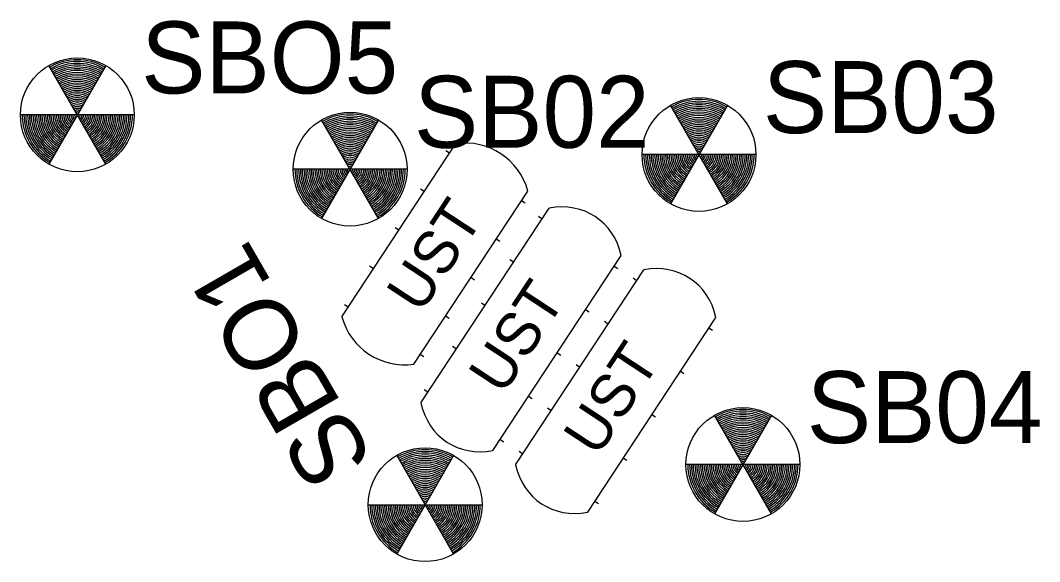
# Model space of a CAD drawing. Extents: x 557444 to 557718, y 506539 to 506965.
# Drawn here: x 557447.4 to 557504, y 506628.1 to 506658.1 of the extents above; entities that cross this region are included whole.
import ezdxf

# ---------------------------------------------------------------- set-up
doc = ezdxf.new("R2010")
doc.units = 0
doc.layers.add('Exist Roads EOP Cogo Number', color=7, linetype='Continuous')
doc.layers.add('Exist Roads EOP Cogo Point CELL', color=7, linetype='Continuous')

msp = doc.modelspace()

# ---------------------------------------------------------------- linework, layer by layer
at = {"layer": 'Exist Roads EOP Cogo Number'}
for p, q in [((557465.227, 506641.678), (557471.561, 506651.301)), ((557471.209, 506650.766), (557471.008, 506650.898)), ((557469.236, 506639.039), (557475.57, 506648.661)), ((557469.801, 506648.628), (557469.601, 506648.76)), ((557475.419, 506647.995), (557475.218, 506648.127)), ((557469.617, 506636.887), (557476.743, 506647.712)), ((557476.347, 506647.111), (557476.147, 506647.243)), ((557468.394, 506646.489), (557468.193, 506646.621)), ((557474.011, 506645.857), (557473.811, 506645.989)), ((557473.627, 506634.248), (557480.752, 506645.073)), ((557474.764, 506644.705), (557474.563, 506644.837)), ((557466.977, 506644.352), (557466.777, 506644.484)), ((557474.877, 506633.457), (557482.002, 506644.282)), ((557480.557, 506644.34), (557480.357, 506644.472)), ((557472.604, 506643.718), (557472.403, 506643.85)), ((557481.606, 506643.681), (557481.406, 506643.813)), ((557465.579, 506642.213), (557465.378, 506642.345)), ((557473.18, 506642.299), (557472.98, 506642.431)), ((557478.974, 506641.934), (557478.773, 506642.066)), ((557471.196, 506641.58), (557470.996, 506641.712)), ((557478.886, 506630.818), (557486.012, 506641.643)), ((557480.023, 506641.275), (557479.822, 506641.407)), ((557485.816, 506640.91), (557485.616, 506641.042)), ((557469.789, 506639.442), (557469.588, 506639.574)), ((557471.587, 506639.895), (557471.387, 506640.027)), ((557477.39, 506639.528), (557477.19, 506639.66)), ((557478.439, 506638.87), (557478.239, 506639.002)), ((557484.233, 506638.504), (557484.032, 506638.636)), ((557470.013, 506637.488), (557469.813, 506637.62)), ((557475.807, 506637.123), (557475.606, 506637.255)), ((557476.846, 506636.465), (557476.646, 506636.597)), ((557482.649, 506636.099), (557482.449, 506636.231)), ((557474.223, 506634.717), (557474.023, 506634.849)), ((557475.272, 506634.059), (557475.072, 506634.19)), ((557481.066, 506633.693), (557480.865, 506633.825)), ((557479.482, 506631.287), (557479.282, 506631.419))]:
    msp.add_line(p, q, dxfattribs=at)
for centre, major_axis, ratio in [((557471.818, 506647.327), (-2.244, -3.409), 0.9375), ((557476.782, 506643.406), (-2.524, -3.835), 0.833333), ((557482.041, 506639.977), (-2.524, -3.835), 0.833333), ((557468.979, 506643.013), (2.244, 3.409), 0.9375), ((557473.588, 506638.553), (2.524, 3.835), 0.833333), ((557478.847, 506635.124), (2.524, 3.835), 0.833333)]:
    msp.add_ellipse(centre, major_axis=major_axis, ratio=ratio, start_param=2.463448, end_param=3.819737, dxfattribs=at)
at = {"layer": 'Exist Roads EOP Cogo Point CELL'}
for p, q in [((557452.123, 506650.157), (557448.961, 506655.634)), ((557452.123, 506655.634), (557448.961, 506650.157)), ((557486.649, 506647.951), (557483.487, 506653.428)), ((557486.649, 506653.428), (557483.487, 506647.951)), ((557453.704, 506652.895), (557447.38, 506652.895)), ((557467.273, 506647.137), (557464.111, 506652.614)), ((557467.273, 506652.614), (557464.111, 506647.137)), ((557488.23, 506650.69), (557481.906, 506650.69)), ((557468.854, 506649.875), (557462.53, 506649.875)), ((557489.089, 506630.729), (557485.927, 506636.206)), ((557489.089, 506636.206), (557485.927, 506630.729)), ((557468.279, 506633.974), (557471.441, 506628.497)), ((557471.441, 506633.974), (557468.279, 506628.497)), ((557490.67, 506633.468), (557484.346, 506633.468)), ((557466.698, 506631.236), (557473.022, 506631.236))]:
    msp.add_line(p, q, dxfattribs=at)
for centre in [(557450.542, 506652.895), (557485.068, 506650.69), (557465.692, 506649.875), (557487.508, 506633.468), (557469.86, 506631.236)]:
    msp.add_circle(centre, 3.162, dxfattribs=at)
for centre, radius, start, end in [((557450.542, 506652.895), 3.062, 60, 120), ((557450.542, 506652.895), 2.962, 60, 120), ((557450.542, 506652.895), 2.862, 60, 120), ((557450.542, 506652.895), 2.762, 60, 120), ((557450.542, 506652.895), 2.662, 60, 120), ((557450.542, 506652.895), 2.562, 60, 120), ((557450.542, 506652.895), 2.462, 60, 120), ((557450.542, 506652.895), 2.362, 60, 120), ((557450.542, 506652.895), 2.262, 60, 120), ((557450.542, 506652.895), 2.162, 60, 120), ((557450.542, 506652.895), 2.062, 60, 120), ((557450.542, 506652.895), 1.962, 60, 120), ((557450.542, 506652.895), 1.862, 60, 120), ((557450.542, 506652.895), 1.762, 60, 120), ((557450.542, 506652.895), 1.662, 60, 120), ((557450.542, 506652.895), 1.562, 60, 120), ((557450.542, 506652.895), 1.462, 60, 120), ((557450.542, 506652.895), 1.362, 60, 120), ((557450.542, 506652.895), 1.262, 60, 120), ((557450.542, 506652.895), 1.162, 60, 120), ((557450.542, 506652.895), 1.062, 60, 120), ((557450.542, 506652.895), 0.962, 60, 120), ((557450.542, 506652.895), 0.862, 60, 120), ((557450.542, 506652.895), 0.762, 60, 120), ((557485.068, 506650.69), 3.062, 60, 120), ((557450.542, 506652.895), 0.662, 60, 120), ((557450.542, 506652.895), 0.562, 60, 120), ((557450.542, 506652.895), 0.462, 60, 120), ((557450.542, 506652.895), 0.362, 60, 120), ((557450.542, 506652.895), 0.262, 60, 120), ((557485.068, 506650.69), 2.962, 60, 120), ((557485.068, 506650.69), 2.862, 60, 120), ((557485.068, 506650.69), 2.762, 60, 120), ((557485.068, 506650.69), 2.662, 60, 120), ((557485.068, 506650.69), 2.562, 60, 120), ((557485.068, 506650.69), 2.462, 60, 120), ((557450.542, 506652.895), 3.062, 180, 240), ((557450.542, 506652.895), 2.962, 180, 240), ((557450.542, 506652.895), 2.862, 180, 240), ((557450.542, 506652.895), 2.762, 180, 240), ((557450.542, 506652.895), 2.662, 180, 240), ((557450.542, 506652.895), 2.562, 180, 240), ((557450.542, 506652.895), 2.462, 180, 240), ((557450.542, 506652.895), 2.362, 180, 240), ((557450.542, 506652.895), 2.262, 180, 240), ((557450.542, 506652.895), 2.162, 180, 240), ((557450.542, 506652.895), 2.062, 180, 240), ((557450.542, 506652.895), 1.962, 180, 240), ((557450.542, 506652.895), 1.862, 180, 240), ((557450.542, 506652.895), 1.762, 180, 240), ((557450.542, 506652.895), 1.662, 180, 240), ((557450.542, 506652.895), 1.562, 180, 240), ((557450.542, 506652.895), 1.462, 180, 240), ((557450.542, 506652.895), 1.362, 180, 240), ((557450.542, 506652.895), 1.262, 180, 240), ((557450.542, 506652.895), 1.162, 180, 240), ((557450.542, 506652.895), 1.062, 180, 240), ((557450.542, 506652.895), 0.962, 180, 240), ((557450.542, 506652.895), 0.862, 180, 240), ((557450.542, 506652.895), 0.762, 180, 240), ((557450.542, 506652.895), 0.662, 180, 240), ((557450.542, 506652.895), 0.562, 180, 240), ((557450.542, 506652.895), 0.462, 180, 240), ((557450.542, 506652.895), 0.362, 180, 240), ((557450.542, 506652.895), 0.262, 180, 240), ((557450.542, 506652.895), 0.162, 180, 240), ((557450.542, 506652.895), 0.162, 60, 120), ((557450.542, 506652.895), 0.162, 300, 0), ((557450.542, 506652.895), 0.262, 300, 0), ((557450.542, 506652.895), 0.362, 300, 0), ((557450.542, 506652.895), 0.462, 300, 0), ((557450.542, 506652.895), 0.562, 300, 360), ((557450.542, 506652.895), 0.662, 300, 0), ((557450.542, 506652.895), 0.762, 300, 360), ((557450.542, 506652.895), 0.862, 300, 0), ((557450.542, 506652.895), 0.962, 300, 0), ((557450.542, 506652.895), 1.062, 300, 0), ((557450.542, 506652.895), 1.162, 300, 0), ((557450.542, 506652.895), 1.262, 300, 0), ((557450.542, 506652.895), 1.362, 300, 0), ((557450.542, 506652.895), 1.462, 300, 0), ((557450.542, 506652.895), 1.562, 300, 0), ((557450.542, 506652.895), 1.662, 300, 0), ((557450.542, 506652.895), 1.762, 300, 0), ((557450.542, 506652.895), 1.862, 300, 0), ((557450.542, 506652.895), 1.962, 300, 0), ((557450.542, 506652.895), 2.062, 300, 360), ((557450.542, 506652.895), 2.162, 300, 0), ((557450.542, 506652.895), 2.262, 300, 0), ((557450.542, 506652.895), 2.362, 300, 0), ((557450.542, 506652.895), 2.462, 300, 0), ((557450.542, 506652.895), 2.562, 300, 0), ((557450.542, 506652.895), 2.662, 300, 0), ((557450.542, 506652.895), 2.762, 300, 360), ((557450.542, 506652.895), 2.862, 300, 0), ((557450.542, 506652.895), 2.962, 300, 0), ((557450.542, 506652.895), 3.062, 300, 0), ((557465.692, 506649.875), 3.062, 60, 120), ((557465.692, 506649.875), 2.962, 60, 120), ((557465.692, 506649.875), 2.862, 60, 120), ((557465.692, 506649.875), 2.762, 60, 120), ((557465.692, 506649.875), 2.662, 60, 120), ((557485.068, 506650.69), 2.362, 60, 120), ((557485.068, 506650.69), 2.262, 60, 120), ((557485.068, 506650.69), 2.162, 60, 120), ((557485.068, 506650.69), 2.062, 60, 120), ((557485.068, 506650.69), 1.962, 60, 120), ((557485.068, 506650.69), 1.862, 60, 120), ((557465.692, 506649.875), 2.562, 60, 120), ((557465.692, 506649.875), 2.462, 60, 120), ((557465.692, 506649.875), 2.362, 60, 120), ((557465.692, 506649.875), 2.262, 60, 120), ((557465.692, 506649.875), 2.162, 60, 120), ((557485.068, 506650.69), 1.762, 60, 120), ((557485.068, 506650.69), 1.662, 60, 120), ((557485.068, 506650.69), 1.562, 60, 120), ((557485.068, 506650.69), 1.462, 60, 120), ((557485.068, 506650.69), 1.362, 60, 120), ((557465.692, 506649.875), 2.062, 60, 120), ((557465.692, 506649.875), 1.962, 60, 120), ((557465.692, 506649.875), 1.862, 60, 120), ((557465.692, 506649.875), 1.762, 60, 120), ((557465.692, 506649.875), 1.662, 60, 120), ((557465.692, 506649.875), 1.562, 60, 120), ((557485.068, 506650.69), 1.262, 60, 120), ((557485.068, 506650.69), 1.162, 60, 120), ((557485.068, 506650.69), 1.062, 60, 120), ((557485.068, 506650.69), 0.962, 60, 120), ((557485.068, 506650.69), 0.862, 60, 120), ((557485.068, 506650.69), 0.762, 60, 120), ((557465.692, 506649.875), 1.462, 60, 120), ((557465.692, 506649.875), 1.362, 60, 120), ((557465.692, 506649.875), 1.262, 60, 120), ((557465.692, 506649.875), 1.162, 60, 120), ((557465.692, 506649.875), 1.062, 60, 120), ((557465.692, 506649.875), 0.962, 60, 120), ((557485.068, 506650.69), 0.662, 60, 120), ((557485.068, 506650.69), 0.562, 60, 120), ((557485.068, 506650.69), 0.462, 60, 120), ((557485.068, 506650.69), 0.362, 60, 120), ((557485.068, 506650.69), 0.262, 60, 120), ((557485.068, 506650.69), 0.162, 60, 120), ((557465.692, 506649.875), 0.862, 60, 120), ((557465.692, 506649.875), 0.762, 60, 120), ((557465.692, 506649.875), 0.662, 60, 120), ((557465.692, 506649.875), 0.562, 60, 120), ((557465.692, 506649.875), 0.462, 60, 120), ((557485.068, 506650.69), 3.062, 180, 240), ((557485.068, 506650.69), 2.962, 180, 240), ((557485.068, 506650.69), 2.862, 180, 240), ((557485.068, 506650.69), 2.762, 180, 240), ((557485.068, 506650.69), 2.662, 180, 240), ((557485.068, 506650.69), 2.562, 180, 240), ((557485.068, 506650.69), 2.462, 180, 240), ((557485.068, 506650.69), 2.362, 180, 240), ((557485.068, 506650.69), 2.262, 180, 240), ((557485.068, 506650.69), 2.162, 180, 240), ((557485.068, 506650.69), 2.062, 180, 240), ((557485.068, 506650.69), 1.962, 180, 240), ((557485.068, 506650.69), 1.862, 180, 240), ((557485.068, 506650.69), 1.762, 180, 240), ((557485.068, 506650.69), 1.662, 180, 240), ((557485.068, 506650.69), 1.562, 180, 240), ((557485.068, 506650.69), 1.462, 180, 240), ((557485.068, 506650.69), 1.362, 180, 240), ((557485.068, 506650.69), 1.262, 180, 240), ((557485.068, 506650.69), 1.162, 180, 240), ((557485.068, 506650.69), 1.062, 180, 240), ((557485.068, 506650.69), 0.962, 180, 240), ((557485.068, 506650.69), 0.862, 180, 240), ((557485.068, 506650.69), 0.762, 180, 240), ((557485.068, 506650.69), 0.662, 180, 240), ((557485.068, 506650.69), 0.562, 180, 240), ((557485.068, 506650.69), 0.462, 180, 240), ((557485.068, 506650.69), 0.362, 180, 240), ((557485.068, 506650.69), 0.262, 180, 240), ((557485.068, 506650.69), 0.162, 180, 240), ((557485.068, 506650.69), 0.162, 300, 0), ((557485.068, 506650.69), 0.262, 300, 0), ((557485.068, 506650.69), 0.362, 300, 0), ((557485.068, 506650.69), 0.462, 300, 0), ((557485.068, 506650.69), 0.562, 300, 360), ((557485.068, 506650.69), 0.662, 300, 0), ((557485.068, 506650.69), 0.762, 300, 360), ((557485.068, 506650.69), 0.862, 300, 0), ((557485.068, 506650.69), 0.962, 300, 0), ((557485.068, 506650.69), 1.062, 300, 0), ((557485.068, 506650.69), 1.162, 300, 0), ((557485.068, 506650.69), 1.262, 300, 0), ((557485.068, 506650.69), 1.362, 300, 0), ((557485.068, 506650.69), 1.462, 300, 0), ((557485.068, 506650.69), 1.562, 300, 0), ((557485.068, 506650.69), 1.662, 300, 0), ((557485.068, 506650.69), 1.762, 300, 0), ((557485.068, 506650.69), 1.862, 300, 0), ((557485.068, 506650.69), 1.962, 300, 0), ((557485.068, 506650.69), 2.062, 300, 360), ((557485.068, 506650.69), 2.162, 300, 0), ((557485.068, 506650.69), 2.262, 300, 0), ((557485.068, 506650.69), 2.362, 300, 0), ((557485.068, 506650.69), 2.462, 300, 0), ((557485.068, 506650.69), 2.562, 300, 0), ((557485.068, 506650.69), 2.662, 300, 0), ((557485.068, 506650.69), 2.762, 300, 360), ((557485.068, 506650.69), 2.862, 300, 0), ((557485.068, 506650.69), 2.962, 300, 0), ((557485.068, 506650.69), 3.062, 300, 0), ((557465.692, 506649.875), 3.062, 180, 240), ((557465.692, 506649.875), 2.962, 180, 240), ((557465.692, 506649.875), 2.862, 180, 240), ((557465.692, 506649.875), 2.762, 180, 240), ((557465.692, 506649.875), 2.662, 180, 240), ((557465.692, 506649.875), 2.562, 180, 240), ((557465.692, 506649.875), 2.462, 180, 240), ((557465.692, 506649.875), 2.362, 180, 240), ((557465.692, 506649.875), 2.262, 180, 240), ((557465.692, 506649.875), 2.162, 180, 240), ((557465.692, 506649.875), 2.062, 180, 240), ((557465.692, 506649.875), 1.962, 180, 240), ((557465.692, 506649.875), 1.862, 180, 240), ((557465.692, 506649.875), 1.762, 180, 240), ((557465.692, 506649.875), 1.662, 180, 240), ((557465.692, 506649.875), 1.562, 180, 240), ((557465.692, 506649.875), 1.462, 180, 240), ((557465.692, 506649.875), 1.362, 180, 240), ((557465.692, 506649.875), 1.262, 180, 240), ((557465.692, 506649.875), 1.162, 180, 240), ((557465.692, 506649.875), 1.062, 180, 240), ((557465.692, 506649.875), 0.962, 180, 240), ((557465.692, 506649.875), 0.862, 180, 240), ((557465.692, 506649.875), 0.762, 180, 240), ((557465.692, 506649.875), 0.662, 180, 240), ((557465.692, 506649.875), 0.562, 180, 240), ((557465.692, 506649.875), 0.462, 180, 240), ((557465.692, 506649.875), 0.362, 180, 240), ((557465.692, 506649.875), 0.262, 180, 240), ((557465.692, 506649.875), 0.362, 60, 120), ((557465.692, 506649.875), 0.162, 180, 240), ((557465.692, 506649.875), 0.262, 60, 120), ((557465.692, 506649.875), 0.162, 60, 120), ((557465.692, 506649.875), 0.162, 300, 0), ((557465.692, 506649.875), 0.262, 300, 0), ((557465.692, 506649.875), 0.362, 300, 0), ((557465.692, 506649.875), 0.462, 300, 0), ((557465.692, 506649.875), 0.562, 300, 360), ((557465.692, 506649.875), 0.662, 300, 0), ((557465.692, 506649.875), 0.762, 300, 360), ((557465.692, 506649.875), 0.862, 300, 0), ((557465.692, 506649.875), 0.962, 300, 0), ((557465.692, 506649.875), 1.062, 300, 0), ((557465.692, 506649.875), 1.162, 300, 0), ((557465.692, 506649.875), 1.262, 300, 0), ((557465.692, 506649.875), 1.362, 300, 0), ((557465.692, 506649.875), 1.462, 300, 0), ((557465.692, 506649.875), 1.562, 300, 0), ((557465.692, 506649.875), 1.662, 300, 0), ((557465.692, 506649.875), 1.762, 300, 0), ((557465.692, 506649.875), 1.862, 300, 0), ((557465.692, 506649.875), 1.962, 300, 0), ((557465.692, 506649.875), 2.062, 300, 360), ((557465.692, 506649.875), 2.162, 300, 0), ((557465.692, 506649.875), 2.262, 300, 0), ((557465.692, 506649.875), 2.362, 300, 0), ((557465.692, 506649.875), 2.462, 300, 0), ((557465.692, 506649.875), 2.562, 300, 0), ((557465.692, 506649.875), 2.662, 300, 0), ((557465.692, 506649.875), 2.762, 300, 360), ((557465.692, 506649.875), 2.862, 300, 0), ((557465.692, 506649.875), 2.962, 300, 0), ((557465.692, 506649.875), 3.062, 300, 0), ((557487.508, 506633.468), 3.062, 60, 120), ((557487.508, 506633.468), 2.962, 60, 120), ((557487.508, 506633.468), 2.862, 60, 120), ((557487.508, 506633.468), 2.762, 60, 120), ((557487.508, 506633.468), 2.662, 60, 120), ((557487.508, 506633.468), 2.562, 60, 120), ((557487.508, 506633.468), 2.462, 60, 120), ((557487.508, 506633.468), 2.362, 60, 120), ((557487.508, 506633.468), 2.262, 60, 120), ((557487.508, 506633.468), 2.162, 60, 120), ((557487.508, 506633.468), 2.062, 60, 120), ((557487.508, 506633.468), 1.962, 60, 120), ((557487.508, 506633.468), 1.862, 60, 120), ((557487.508, 506633.468), 1.762, 60, 120), ((557487.508, 506633.468), 1.662, 60, 120), ((557487.508, 506633.468), 1.562, 60, 120), ((557487.508, 506633.468), 1.462, 60, 120), ((557487.508, 506633.468), 1.362, 60, 120), ((557487.508, 506633.468), 1.262, 60, 120), ((557487.508, 506633.468), 1.162, 60, 120), ((557487.508, 506633.468), 1.062, 60, 120), ((557487.508, 506633.468), 0.962, 60, 120), ((557469.86, 506631.236), 3.062, 60, 120), ((557469.86, 506631.236), 2.962, 60, 120), ((557469.86, 506631.236), 2.862, 60, 120), ((557469.86, 506631.236), 2.762, 60, 120), ((557469.86, 506631.236), 2.662, 60, 120), ((557487.508, 506633.468), 0.862, 60, 120), ((557487.508, 506633.468), 0.762, 60, 120), ((557487.508, 506633.468), 0.662, 60, 120), ((557487.508, 506633.468), 0.562, 60, 120), ((557487.508, 506633.468), 0.462, 60, 120), ((557469.86, 506631.236), 2.562, 60, 120), ((557469.86, 506631.236), 2.462, 60, 120), ((557469.86, 506631.236), 2.362, 60, 120), ((557469.86, 506631.236), 2.262, 60, 120), ((557469.86, 506631.236), 2.162, 60, 120), ((557469.86, 506631.236), 2.062, 60, 120), ((557487.508, 506633.468), 3.062, 180, 240), ((557487.508, 506633.468), 2.962, 180, 240), ((557487.508, 506633.468), 2.862, 180, 240), ((557487.508, 506633.468), 2.762, 180, 240), ((557487.508, 506633.468), 2.662, 180, 240), ((557487.508, 506633.468), 2.562, 180, 240), ((557487.508, 506633.468), 2.462, 180, 240), ((557487.508, 506633.468), 2.362, 180, 240), ((557487.508, 506633.468), 2.262, 180, 240), ((557487.508, 506633.468), 2.162, 180, 240), ((557487.508, 506633.468), 2.062, 180, 240), ((557487.508, 506633.468), 1.962, 180, 240), ((557487.508, 506633.468), 1.862, 180, 240), ((557487.508, 506633.468), 1.762, 180, 240), ((557487.508, 506633.468), 1.662, 180, 240), ((557487.508, 506633.468), 1.562, 180, 240), ((557487.508, 506633.468), 1.462, 180, 240), ((557487.508, 506633.468), 1.362, 180, 240), ((557487.508, 506633.468), 1.262, 180, 240), ((557487.508, 506633.468), 1.162, 180, 240), ((557487.508, 506633.468), 1.062, 180, 240), ((557487.508, 506633.468), 0.962, 180, 240), ((557487.508, 506633.468), 0.862, 180, 240), ((557487.508, 506633.468), 0.762, 180, 240), ((557487.508, 506633.468), 0.662, 180, 240), ((557487.508, 506633.468), 0.562, 180, 240), ((557487.508, 506633.468), 0.462, 180, 240), ((557487.508, 506633.468), 0.362, 180, 240), ((557487.508, 506633.468), 0.262, 180, 240), ((557487.508, 506633.468), 0.362, 60, 120), ((557487.508, 506633.468), 0.162, 180, 240), ((557487.508, 506633.468), 0.262, 60, 120), ((557487.508, 506633.468), 0.162, 60, 120), ((557487.508, 506633.468), 0.162, 300, 0), ((557487.508, 506633.468), 0.262, 300, 0), ((557487.508, 506633.468), 0.362, 300, 0), ((557487.508, 506633.468), 0.462, 300, 0), ((557487.508, 506633.468), 0.562, 300, 360), ((557487.508, 506633.468), 0.662, 300, 0), ((557487.508, 506633.468), 0.762, 300, 360), ((557487.508, 506633.468), 0.862, 300, 0), ((557487.508, 506633.468), 0.962, 300, 0), ((557487.508, 506633.468), 1.062, 300, 0), ((557487.508, 506633.468), 1.162, 300, 0), ((557487.508, 506633.468), 1.262, 300, 0), ((557487.508, 506633.468), 1.362, 300, 0), ((557487.508, 506633.468), 1.462, 300, 0), ((557487.508, 506633.468), 1.562, 300, 0), ((557487.508, 506633.468), 1.662, 300, 0), ((557487.508, 506633.468), 1.762, 300, 0), ((557487.508, 506633.468), 1.862, 300, 0), ((557487.508, 506633.468), 1.962, 300, 0), ((557487.508, 506633.468), 2.062, 300, 360), ((557487.508, 506633.468), 2.162, 300, 0), ((557487.508, 506633.468), 2.262, 300, 0), ((557487.508, 506633.468), 2.362, 300, 0), ((557487.508, 506633.468), 2.462, 300, 0), ((557487.508, 506633.468), 2.562, 300, 0), ((557487.508, 506633.468), 2.662, 300, 0), ((557487.508, 506633.468), 2.762, 300, 360), ((557487.508, 506633.468), 2.862, 300, 0), ((557487.508, 506633.468), 2.962, 300, 0), ((557487.508, 506633.468), 3.062, 300, 0), ((557469.86, 506631.236), 1.962, 60, 120), ((557469.86, 506631.236), 1.862, 60, 120), ((557469.86, 506631.236), 1.762, 60, 120), ((557469.86, 506631.236), 1.662, 60, 120), ((557469.86, 506631.236), 1.562, 60, 120), ((557469.86, 506631.236), 1.462, 60, 120), ((557469.86, 506631.236), 1.362, 60, 120), ((557469.86, 506631.236), 1.262, 60, 120), ((557469.86, 506631.236), 1.162, 60, 120), ((557469.86, 506631.236), 1.062, 60, 120), ((557469.86, 506631.236), 0.962, 60, 120), ((557469.86, 506631.236), 0.862, 60, 120), ((557469.86, 506631.236), 0.762, 60, 120), ((557469.86, 506631.236), 0.662, 60, 120), ((557469.86, 506631.236), 0.562, 60, 120), ((557469.86, 506631.236), 0.462, 60, 120), ((557469.86, 506631.236), 0.362, 60, 120), ((557469.86, 506631.236), 3.062, 180, 240), ((557469.86, 506631.236), 2.962, 180, 240), ((557469.86, 506631.236), 2.862, 180, 240), ((557469.86, 506631.236), 2.762, 180, 240), ((557469.86, 506631.236), 2.662, 180, 240), ((557469.86, 506631.236), 2.562, 180, 240), ((557469.86, 506631.236), 2.462, 180, 240), ((557469.86, 506631.236), 2.362, 180, 240), ((557469.86, 506631.236), 2.262, 180, 240), ((557469.86, 506631.236), 2.162, 180, 240), ((557469.86, 506631.236), 2.062, 180, 240), ((557469.86, 506631.236), 1.962, 180, 240), ((557469.86, 506631.236), 1.862, 180, 240), ((557469.86, 506631.236), 1.762, 180, 240), ((557469.86, 506631.236), 1.662, 180, 240), ((557469.86, 506631.236), 1.562, 180, 240), ((557469.86, 506631.236), 1.462, 180, 240), ((557469.86, 506631.236), 1.362, 180, 240), ((557469.86, 506631.236), 1.262, 180, 240), ((557469.86, 506631.236), 1.162, 180, 240), ((557469.86, 506631.236), 1.062, 180, 240), ((557469.86, 506631.236), 0.962, 180, 240), ((557469.86, 506631.236), 0.862, 180, 240), ((557469.86, 506631.236), 0.762, 180, 240), ((557469.86, 506631.236), 0.662, 180, 240), ((557469.86, 506631.236), 0.562, 180, 240), ((557469.86, 506631.236), 0.462, 180, 240), ((557469.86, 506631.236), 0.362, 180, 240), ((557469.86, 506631.236), 0.262, 180, 240), ((557469.86, 506631.236), 0.162, 180, 240), ((557469.86, 506631.236), 0.262, 60, 120), ((557469.86, 506631.236), 0.162, 60, 120), ((557469.86, 506631.236), 0.162, 300, 360), ((557469.86, 506631.236), 0.262, 300, 360), ((557469.86, 506631.236), 0.362, 300, 360), ((557469.86, 506631.236), 0.462, 300, 360), ((557469.86, 506631.236), 0.562, 300, 360), ((557469.86, 506631.236), 0.662, 300, 360), ((557469.86, 506631.236), 0.762, 300, 360), ((557469.86, 506631.236), 0.862, 300, 360), ((557469.86, 506631.236), 0.962, 300, 360), ((557469.86, 506631.236), 1.062, 300, 360), ((557469.86, 506631.236), 1.162, 300, 360), ((557469.86, 506631.236), 1.262, 300, 360), ((557469.86, 506631.236), 1.362, 300, 360), ((557469.86, 506631.236), 1.462, 300, 360), ((557469.86, 506631.236), 1.562, 300, 360), ((557469.86, 506631.236), 1.662, 300, 360), ((557469.86, 506631.236), 1.762, 300, 0), ((557469.86, 506631.236), 1.862, 300, 0), ((557469.86, 506631.236), 1.962, 300, 360), ((557469.86, 506631.236), 2.062, 300, 360), ((557469.86, 506631.236), 2.162, 300, 360), ((557469.86, 506631.236), 2.262, 300, 360), ((557469.86, 506631.236), 2.362, 300, 360), ((557469.86, 506631.236), 2.462, 300, 360), ((557469.86, 506631.236), 2.562, 300, 360), ((557469.86, 506631.236), 2.662, 300, 360), ((557469.86, 506631.236), 2.762, 300, 360), ((557469.86, 506631.236), 2.862, 300, 360), ((557469.86, 506631.236), 2.962, 300, 360), ((557469.86, 506631.236), 3.062, 300, 360)]:
    msp.add_arc(centre, radius, start, end, dxfattribs=at)

# ---------------------------------------------------------------- texts
at = {"layer": 'Exist Roads EOP Cogo Number'}
for p in [(557469.605, 506641.782), (557474.167, 506637.251), (557479.427, 506633.822)]:
    msp.add_text('UST', height=2.4, rotation=56.6456, dxfattribs=at).set_placement(p)
at = {"layer": 'Exist Roads EOP Cogo Point CELL'}
for s, p in [('SBO5', (557454.09, 506654.084)), ('SB03', (557488.617, 506651.879)), ('SB02', (557469.24, 506651.065)), ('SB04', (557491.057, 506634.657))]:
    msp.add_text(s, height=4, dxfattribs=at).set_placement(p)
msp.add_text('SBO1', height=4, rotation=120, dxfattribs=at).set_placement((557467.056, 506633.714))

doc.saveas('drawing.dxf')
